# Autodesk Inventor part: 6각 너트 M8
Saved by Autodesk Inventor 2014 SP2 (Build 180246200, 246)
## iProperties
Created: 2025-07
Part Number: 6각 너트 M8
Material: Generic
Document SubType Name: Modeling
Designer: Administrator
Density: 1 g/cm^3
Appearance: Default
Author: Administrator
Author: jhkim
Description: 6각 너트 및 6각 가는 너트
Creation Date: 2025-06-11
Sending System: Autodesk Inventor 2026
Preprocessor: ST-DEVELOPER v20.1
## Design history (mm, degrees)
node "6각 너트 M81"
body "Solid1"
node "기준1"
